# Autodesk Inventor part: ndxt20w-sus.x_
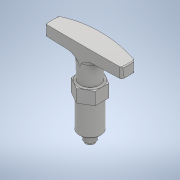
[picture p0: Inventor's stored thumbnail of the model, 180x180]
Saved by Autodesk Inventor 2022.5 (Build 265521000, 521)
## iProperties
Created: 2018-04
Part Number: ndxt20w-sus.x_
Material: 一般
Document SubType Name: Modeling
Designer: imaocorp
Density: 1 g/cm^3
Appearance: 既定
Sending System: SOLIDWORKS 2016-2016286
MC: AMD64
MC_MODEL: AMD64 Family 21 Model 2 Stepping 0, AuthenticAMD
OS: Windows_NT
FRU: Parasolid Version 28.0, build 224,  7-29-2016
FORMAT: text
GUISE: transmit
KEY: ndxt20w-sus
FILE: ndxt20w-sus.x_t
DATE: Wed Apr 25 10:16:29 2018
Author: imaocorp
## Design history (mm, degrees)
feature "ndxt20w_01"
node "ソリッド1"
